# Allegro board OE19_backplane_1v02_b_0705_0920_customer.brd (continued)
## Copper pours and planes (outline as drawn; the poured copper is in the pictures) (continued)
GND on IN2 (solid shape): 252.6,114.49 252.95,114.35 253.09,114 253.09,113.1 253.09,113.02 252.59,113.02 252.58,113.1 252.58,113.98 215.02,113.98 215.02,40.85 214.43,39.42 213,38.83 192.99,38.83 191.97,38.93 185.44,38.93 185.2,38.83 40.3,38.83 39.51,39.15 39.44,39.26 39.54,39.34 213,39.34 214.07,39.78 214.51,40.85 214.51,114 214.65,114.35 215,114.49
GND on IN2 (solid shape): 32.6,114.49 32.95,114.35 33.09,114 33.09,113.1 33.53,112.03 34.6,111.59 36.5,111.59 36.85,111.45 36.99,111.1 36.99,83.5 36.85,83.15 36.5,83.01 34.6,83.01 33.53,82.57 33.09,81.5 33.09,70.25 33.53,69.18 34.6,68.74 36.5,68.74 36.85,68.6 36.99,68.25 36.99,41.14 36.92,41.04 36.81,41.08 36.48,41.51 36.48,68.23 34.6,68.23 33.17,68.82 32.58,70.25 32.58,81.5 33.17,82.93 34.6,83.52 36.48,83.52 36.48,111.08 34.6,111.08 33.17,111.67 32.58,113.1 32.58,113.98 1.02,113.98 1.02,99.1 0.51,99.1 0.51,114 0.65,114.35 1,114.49
GND on IN2 (solid shape): outline of 1522 points within 214.61,0.64 256.48,114.25
GND on IN2 (solid shape): outline of 4441 points within 1.98,10.28 161.7,55.87
GND on GND1 (solid shape): outline of 3510 points within 0.51,0.51 256.99,114.49
P3V3_RMC_STBY on TOP (solid shape): 166.85,33.05 166.85,32.13 166.59,31.87 166.02,31.87 165.76,32.13 165.76,32.68 165.67,32.68 165.49,32.85 163.45,32.85 162.58,31.98 162.58,31.47 162.32,31.21 162.23,31.21 162.23,31.24 160.81,31.24 160.81,31.19 160.49,31.19 160.27,30.97 160.27,29.18 160.36,29.09 162.31,29.09 162.43,28.97 162.43,27.02 162.18,26.77 161.12,26.77 161.07,26.82 161.07,27.77 160.83,28.01 157.87,28.01 157.69,27.83 157.69,27.52 157.69,27.51 157.66,27.35 157.69,27.19 157.69,27.18 157.69,26.95 157.6,26.85 156.62,26.85 156.27,27.19 156.27,28.67 156.4,28.67 156.73,28.99 157.17,28.99 157.32,29.02 157.45,29.09 157.88,29.09 157.88,29.15 158.44,29.71 158.44,31.18 158.06,31.56 156.04,31.56 155.66,31.93 155.66,33.07 156.01,33.41 166.49,33.41
P3V3_RMC_STBY on BOTTOM (solid shape): 178.71,34.54 178.9,34.51 179.09,34.54 179.1,34.55 180.02,34.55 180.27,34.3 180.27,31.83 180.11,31.67 177.4,31.67 177.4,32.18 177.41,32.18 177.43,32.33 177.41,32.49 177.4,32.49 177.4,33.58 177.41,33.58 177.43,33.74 177.41,33.89 177.4,33.89 177.4,34.25 177.7,34.55 178.7,34.55
P12V_PSU on TOP (solid shape): outline of 1477 points within 221.54,3.74 249.31,111.47
P12V_PSU on TOP (solid shape): outline of 2737 points within 15.35,18.17 143.48,111.12
P12V_PSU on BOTTOM (solid shape): outline of 1620 points within 221.47,3.79 250.72,111.35
P12V_PSU on IN1 (solid shape): outline of 1971 points within 221.47,3.79 250.72,111.35
P12V_PSU on IN1 (solid shape): outline of 2631 points within 18.46,18.43 141.79,108.49
P12V_PSU on VCC (solid shape): outline of 6247 points within 1.02,1.02 256.48,113.98
P12V_PSU on VCC1 (solid shape): outline of 6211 points within 1.02,1.02 256.48,113.98
P12V_PSU on IN2 (solid shape): outline of 1594 points within 221.47,3.79 250.72,111.35
Net_2 on TOP (solid shape): outline of 303 points within 32.15,9.95 43.15,17.45
Net_3 on BOTTOM (solid shape): outline of 303 points within 32.15,9.95 43.15,17.45
Net_34 on BOTTOM (solid shape): outline of 303 points within 199.15,9.95 210.15,17.45
Net_35 on TOP (solid shape): outline of 303 points within 149.15,9.95 160.15,17.45
Net_35 on TOP (solid shape): outline of 303 points within 199.15,9.95 210.15,17.45
Net_36 on BOTTOM (solid shape): outline of 303 points within 149.15,9.95 160.15,17.45
Net_37 on TOP (solid shape): outline of 303 points within 96.15,9.95 107.15,17.45
Net_38 on BOTTOM (solid shape): outline of 303 points within 96.15,9.95 107.15,17.45
Net_39 on TOP (solid shape): outline of 303 points within 220.15,60.45 231.15,67.95
Net_40 on BOTTOM (solid shape): outline of 303 points within 220.15,60.45 231.15,67.95
Net_41 on TOP (solid shape): outline of 303 points within 240.15,71.95 251.15,79.45
Net_42 on BOTTOM (solid shape): outline of 303 points within 240.15,71.95 251.15,79.45
Net_43 on TOP (solid shape): outline of 303 points within 220.15,103.3 231.15,110.8
Net_44 on BOTTOM (solid shape): outline of 303 points within 220.15,103.3 231.15,110.8
Net_45 on TOP (solid shape): outline of 303 points within 0.15,60.45 11.15,67.95
Net_46 on BOTTOM (solid shape): outline of 303 points within 0.15,60.45 11.15,67.95
Net_47 on TOP (solid shape): outline of 303 points within 0.15,103.3 11.15,110.8
Net_48 on BOTTOM (solid shape): outline of 303 points within 0.15,103.3 11.15,110.8
Net_49 on TOP (solid shape): outline of 303 points within 20.15,71.95 31.15,79.45
Net_50 on BOTTOM (solid shape): outline of 303 points within 20.15,71.95 31.15,79.45
TGND on GND (solid shape): outline of 3840 points within 36.11,42.36 222.49,189.64
TGND on VCC (solid shape): outline of 3275 points within 36.11,42.36 222.49,189.64
TGND on VCC1 (solid shape): outline of 3275 points within 36.11,42.36 222.49,189.64
TGND on GND1 (solid shape): outline of 3551 points within 36.11,42.36 222.49,189.64

Small or netless copper shapes (teardrops, artwork), in the pictures only: 1 on TOP, 1 on BOTTOM, 8 on IN1, 9 on IN2

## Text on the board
Ref Des/Silkscreen Top: SLED1/BBU | P/N:DA0S9NTH8B0 | SLED2 | SLED4 | SLED5 | SLED3 | Rev:B
User.39: MARK:TIN LEAD:RECOMMENDED DRILL SIZE FOR 0.5MM FINISHED PTH IS 0.6MM METRIC DRILL OR #74 ENGLISH DRILL.(0.57~0.61) | O:RECOMMENDED DRILL SIZE FOR 0.5MM FINISHED PTH IS 0.6MM METRIC DRILL OR #74 ENGLISH DRILL. | TIN-LEAD:RECOMMENDED DRILL SIZE FOR 0.725MM FINISHED PTH IS 0.81-0.86MM(0.85MM DRILL) | IMMERSION TIN/IMMERSION SILVER/COPPER:RECOMMENDED DRILL SIZE FOR 0.75MM FINISHED PTH IS 0.81-0.86MM(0.85MM DRILL). | GOLD:RECOMMENDED DRILL SIZE FOR 0.745MM FINISHED PTH IS 0.81-0.86MM(0.85MM DRILL) | NON-MARK:RECOMMENDED DRILL SIZE FOR 0.4MM FINISHED PTH IS 0.5MM METRIC DRILL OR #77 ENGLISH DRILL. | NON-MARK:TIN LEAD:RECOMMENDED DRILL SIZE FOR 0.4MM FINISHED PTH IS 0.5MM METRIC DRILL OR #77 ENGLISH DRILL.(0.47~0.51) | COPPER OSP/TIN(IMMERSION):RECOMMENDED DRILL SIZE FOR 0.5MM FINISHED PTH IS 0.6MM METRIC DRILL OR #74 ENGLISH DRILL.(0.54~0.6) | SILVER(IMMERSION):RECOMMENDED DRILL SIZE FOR 0.5MM FINISHED PTH IS 0.6MM METRIC DRILL OR #74 ENGLISH DRILL.(0.54~0.6) | COPPER OSP/TIN(IMMERSION):RECOMMENDED DRILL SIZE FOR 0.4MM FINISHED PTH IS 0.5MM METRIC DRILL OR #77 ENGLISH DRILL.(0.44~0.5) | SILVER(IMMERSION):RECOMMENDED DRILL SIZE FOR 0.4MM FINISHED PTH IS 0.5MM METRIC DRILL OR #77 ENGLISH DRILL.(0.44~0.5)
User.41: FIGURE | SIZE | 10.0 | 15.74 | 19.68 | 29.52 | 138.0 | 204.0 | 221.0 | 39.0 | 85.0 | 105.0 | 107.0 | 125.0 | DRILL CHART: TOP to BOTTOM | ALL UNITS ARE IN MILS | TOLERANCE | +0.0/-10.0 | +1.96/-1.96 | +3.0/-3.0 | +3.0/-0.0 | +2.0/-2.0 | +2.0/-0.0 | PLATED | NON-PLATED | QTY | 51 | 397 | 290 | 105 | 286 | 2 | 5 | 40 | 4 | 10
